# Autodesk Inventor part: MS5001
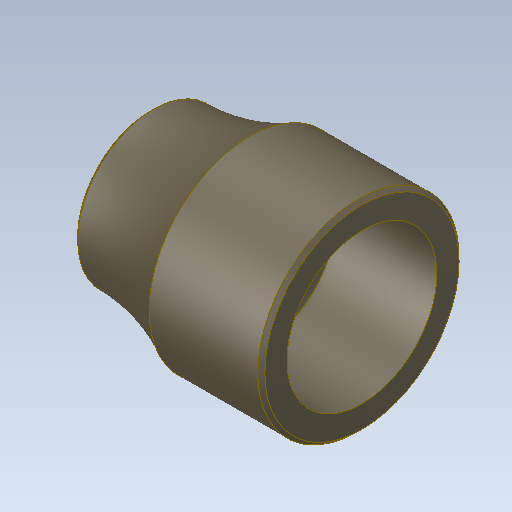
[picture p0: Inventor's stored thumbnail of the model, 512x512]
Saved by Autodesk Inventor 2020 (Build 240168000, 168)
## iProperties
Created: 2015-11
Part Number: MS5001
Material: Ogólny
Document SubType Name: Modeling
Designer: Tomasz
Density: 1 g/cm^3
Appearance: Domyślna
Sending System: SolidWorks 2017
Last Author: Tomasz
Last Saved: 2017-09-17
Author: Tomasz
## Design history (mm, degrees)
feature "Imported1"
node "Bryła1"
